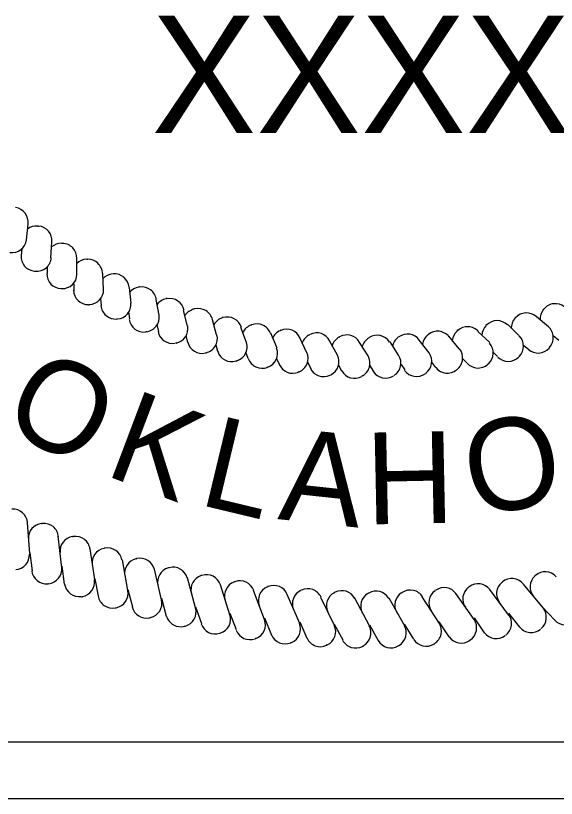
# Model space of a CAD drawing. Extents: x 1458004.1 to 1458040.9, y 194172.7 to 194198.1.
# Drawn here: x 1458038.114 to 1458038.688, y 194176.047 to 194176.879 of the extents above; entities that cross this region are included whole.
import ezdxf

# ---------------------------------------------------------------- set-up
doc = ezdxf.new("R2010")
doc.units = 0
for name, color, linetype in [('Eng_Stamp', 7, 'Continuous'), ('Eng_Stamp_Text_4', 7, 'Continuous'), ('Text_Box_4', 7, 'Continuous')]:
    doc.layers.add(name, color=color, linetype=linetype)

msp = doc.modelspace()

# ---------------------------------------------------------------- linework, layer by layer
at = {"layer": 'Eng_Stamp'}
for p, q in [((1458038.12583, 194176.64083), (1458038.1275, 194176.6575)), ((1458038.13833, 194176.655), (1458038.1375, 194176.655)), ((1458038.12083, 194176.63167), (1458038.12, 194176.62417)), ((1458038.15167, 194176.62167), (1458038.1525, 194176.63833)), ((1458038.16417, 194176.63667), (1458038.16333, 194176.63667)), ((1458038.17917, 194176.60417), (1458038.17917, 194176.62083)), ((1458038.19083, 194176.62), (1458038.19, 194176.62)), ((1458038.13417, 194176.6075), (1458038.135, 194176.6075)), ((1458038.1475, 194176.6125), (1458038.1475, 194176.605)), ((1458038.2075, 194176.5875), (1458038.20667, 194176.605)), ((1458038.2175, 194176.60417), (1458038.2175, 194176.60417)), ((1458038.17583, 194176.59417), (1458038.17583, 194176.58667)), ((1458038.23667, 194176.57333), (1458038.235, 194176.59)), ((1458038.24583, 194176.59083), (1458038.245, 194176.59083)), ((1458038.1625, 194176.58833), (1458038.16333, 194176.58917)), ((1458038.20417, 194176.57833), (1458038.205, 194176.57083)), ((1458038.26667, 194176.56083), (1458038.26333, 194176.5775)), ((1458038.275, 194176.57833), (1458038.27417, 194176.57833)), ((1458038.19167, 194176.57167), (1458038.1925, 194176.57167)), ((1458038.29667, 194176.54917), (1458038.2925, 194176.56583)), ((1458038.30417, 194176.5675), (1458038.30333, 194176.5675)), ((1458038.675, 194176.5675), (1458038.67417, 194176.56667)), ((1458038.22167, 194176.55667), (1458038.2225, 194176.55667)), ((1458038.23417, 194176.56417), (1458038.235, 194176.55667)), ((1458038.33417, 194176.55833), (1458038.33333, 194176.55833)), ((1458038.645, 194176.55833), (1458038.64417, 194176.5575)), ((1458038.68, 194176.54833), (1458038.66667, 194176.55917)), ((1458038.26417, 194176.55083), (1458038.26583, 194176.54333)), ((1458038.3275, 194176.54), (1458038.32333, 194176.55583)), ((1458038.365, 194176.55083), (1458038.36417, 194176.55)), ((1458038.61417, 194176.55083), (1458038.61333, 194176.55)), ((1458038.64833, 194176.53917), (1458038.63667, 194176.55083)), ((1458038.2525, 194176.54333), (1458038.25333, 194176.54333)), ((1458038.35917, 194176.53167), (1458038.35333, 194176.5475)), ((1458038.39167, 194176.52583), (1458038.385, 194176.54167)), ((1458038.39583, 194176.545), (1458038.395, 194176.54417)), ((1458038.42667, 194176.54), (1458038.42583, 194176.54)), ((1458038.5525, 194176.54), (1458038.55167, 194176.54)), ((1458038.58333, 194176.545), (1458038.5825, 194176.54417)), ((1458038.6175, 194176.53167), (1458038.605, 194176.54333)), ((1458038.28417, 194176.53083), (1458038.285, 194176.53167)), ((1458038.295, 194176.53917), (1458038.29667, 194176.53167)), ((1458038.42333, 194176.52083), (1458038.41583, 194176.53667)), ((1458038.45583, 194176.51833), (1458038.4475, 194176.53333)), ((1458038.45833, 194176.5375), (1458038.4575, 194176.5375)), ((1458038.48833, 194176.5175), (1458038.47917, 194176.53167)), ((1458038.49, 194176.53667), (1458038.48917, 194176.53667)), ((1458038.52083, 194176.51833), (1458038.51167, 194176.5325)), ((1458038.52083, 194176.5375), (1458038.52, 194176.5375)), ((1458038.55333, 194176.52083), (1458038.5425, 194176.53417)), ((1458038.585, 194176.525), (1458038.57417, 194176.53833)), ((1458038.685, 194176.53917), (1458038.69083, 194176.53417)), ((1458038.32667, 194176.52917), (1458038.32833, 194176.5225)), ((1458038.6525, 194176.52917), (1458038.65833, 194176.525)), ((1458038.68083, 194176.52583), (1458038.68083, 194176.52667)), ((1458038.31583, 194176.52083), (1458038.31667, 194176.52083)), ((1458038.35833, 194176.52167), (1458038.36083, 194176.515)), ((1458038.39083, 194176.515), (1458038.39417, 194176.50833)), ((1458038.58833, 194176.515), (1458038.59333, 194176.51)), ((1458038.62083, 194176.52167), (1458038.62583, 194176.51667)), ((1458038.64833, 194176.51667), (1458038.64917, 194176.51667)), ((1458038.34833, 194176.51167), (1458038.34917, 194176.5125)), ((1458038.42417, 194176.51083), (1458038.4275, 194176.50417)), ((1458038.45667, 194176.50833), (1458038.46, 194176.50167)), ((1458038.49, 194176.5075), (1458038.49417, 194176.50083)), ((1458038.52333, 194176.50833), (1458038.5275, 194176.5025)), ((1458038.55583, 194176.51083), (1458038.56, 194176.505)), ((1458038.615, 194176.50833), (1458038.61583, 194176.50917)), ((1458038.38083, 194176.505), (1458038.38167, 194176.50583)), ((1458038.41417, 194176.5), (1458038.415, 194176.50083)), ((1458038.54917, 194176.49833), (1458038.55, 194176.49917)), ((1458038.5825, 194176.5025), (1458038.58333, 194176.50333)), ((1458038.44833, 194176.4975), (1458038.44917, 194176.4975)), ((1458038.48167, 194176.49583), (1458038.4825, 194176.49667)), ((1458038.51583, 194176.49667), (1458038.51583, 194176.49667)), ((1458038.12917, 194176.3075), (1458038.12667, 194176.34)), ((1458038.1425, 194176.33917), (1458038.14167, 194176.33917)), ((1458038.16333, 194176.2925), (1458038.15917, 194176.32583)), ((1458038.175, 194176.32583), (1458038.175, 194176.325)), ((1458038.12917, 194176.30833), (1458038.13167, 194176.28917)), ((1458038.19833, 194176.28), (1458038.19333, 194176.3125)), ((1458038.20917, 194176.31333), (1458038.20833, 194176.31333)), ((1458038.23333, 194176.26833), (1458038.2275, 194176.30083)), ((1458038.2425, 194176.3025), (1458038.24167, 194176.30167)), ((1458038.16333, 194176.29417), (1458038.16583, 194176.275)), ((1458038.26917, 194176.25833), (1458038.26167, 194176.29083)), ((1458038.2775, 194176.2925), (1458038.27667, 194176.2925)), ((1458038.31167, 194176.28417), (1458038.31083, 194176.28417)), ((1458038.66583, 194176.28417), (1458038.665, 194176.28333)), ((1458038.14833, 194176.27583), (1458038.14917, 194176.27583)), ((1458038.19833, 194176.28083), (1458038.20167, 194176.2625)), ((1458038.305, 194176.25), (1458038.29667, 194176.28167)), ((1458038.34167, 194176.2425), (1458038.33167, 194176.27417)), ((1458038.34667, 194176.2775), (1458038.34583, 194176.2775)), ((1458038.63083, 194176.2775), (1458038.63083, 194176.27667)), ((1458038.67417, 194176.25), (1458038.65333, 194176.275)), ((1458038.23333, 194176.26917), (1458038.23833, 194176.25083)), ((1458038.37833, 194176.2375), (1458038.36667, 194176.26833)), ((1458038.3825, 194176.2725), (1458038.38167, 194176.2725)), ((1458038.4175, 194176.26833), (1458038.41667, 194176.26833)), ((1458038.45333, 194176.26667), (1458038.4525, 194176.26583)), ((1458038.48917, 194176.26583), (1458038.48833, 194176.265)), ((1458038.525, 194176.26667), (1458038.52417, 194176.26583)), ((1458038.56, 194176.26833), (1458038.55917, 194176.26833)), ((1458038.59583, 194176.2725), (1458038.595, 194176.27167)), ((1458038.6375, 194176.2425), (1458038.6175, 194176.26917)), ((1458038.18417, 194176.26167), (1458038.185, 194176.26167)), ((1458038.26917, 194176.26), (1458038.27417, 194176.24083)), ((1458038.41583, 194176.23333), (1458038.4025, 194176.26417)), ((1458038.4525, 194176.23167), (1458038.43833, 194176.26083)), ((1458038.49, 194176.23083), (1458038.47417, 194176.26)), ((1458038.52667, 194176.23167), (1458038.51083, 194176.26)), ((1458038.56417, 194176.23333), (1458038.54583, 194176.26167)), ((1458038.60083, 194176.2375), (1458038.58167, 194176.265)), ((1458038.22, 194176.25), (1458038.22083, 194176.25)), ((1458038.305, 194176.25083), (1458038.31167, 194176.23333)), ((1458038.67333, 194176.25083), (1458038.68667, 194176.23667)), ((1458038.34167, 194176.24417), (1458038.34833, 194176.22667)), ((1458038.6375, 194176.24417), (1458038.64917, 194176.22917)), ((1458038.25667, 194176.23917), (1458038.2575, 194176.24)), ((1458038.37833, 194176.23917), (1458038.38583, 194176.22083)), ((1458038.41583, 194176.235), (1458038.42333, 194176.2175)), ((1458038.4525, 194176.2325), (1458038.46167, 194176.21583)), ((1458038.52667, 194176.2325), (1458038.53667, 194176.21667)), ((1458038.56333, 194176.235), (1458038.57417, 194176.21917)), ((1458038.60083, 194176.23917), (1458038.61167, 194176.22333)), ((1458038.29333, 194176.23), (1458038.29417, 194176.23083)), ((1458038.49, 194176.23167), (1458038.49917, 194176.215)), ((1458038.67167, 194176.2275), (1458038.67167, 194176.2275)), ((1458038.33083, 194176.2225), (1458038.33167, 194176.22333)), ((1458038.36833, 194176.2175), (1458038.36917, 194176.2175)), ((1458038.59583, 194176.215), (1458038.59667, 194176.21583)), ((1458038.63417, 194176.22083), (1458038.63417, 194176.22083)), ((1458038.40667, 194176.2125), (1458038.40667, 194176.21333)), ((1458038.44417, 194176.21), (1458038.445, 194176.21083)), ((1458038.4825, 194176.20917), (1458038.48333, 194176.20917)), ((1458038.52083, 194176.20917), (1458038.52083, 194176.21)), ((1458038.55833, 194176.21167), (1458038.55917, 194176.21167))]:
    msp.add_line(p, q, dxfattribs=at)
for centre, start, end in [((1458038.11188, 194176.65959), 352.21112, 82.21112), ((1458038.13634, 194176.63987), 85.31452, 128.34659), ((1458038.1372, 194176.6398), 355.31452, 85.31452), ((1458038.11023, 194176.64273), 262.21112, 352.21112), ((1458038.1627, 194176.62144), 88.41792, 131.44999), ((1458038.16356, 194176.62141), 358.41792, 88.41792), ((1458038.13561, 194176.62294), 175.31452, 265.31452), ((1458038.13647, 194176.62287), 265.31452, 355.31452), ((1458038.19002, 194176.60445), 91.52132, 134.55339), ((1458038.19088, 194176.60448), 1.52132, 91.52132), ((1458038.16288, 194176.60449), 178.41792, 268.41792), ((1458038.16375, 194176.60447), 268.41792, 358.41792), ((1458038.21821, 194176.58897), 94.62472, 137.65679), ((1458038.21908, 194176.58904), 4.62472, 94.62472), ((1458038.24721, 194176.57504), 97.72812, 140.76019), ((1458038.24806, 194176.57516), 7.72812, 97.72812), ((1458038.19112, 194176.58754), 181.52132, 271.52132), ((1458038.19198, 194176.58757), 271.52132, 1.52132), ((1458038.22109, 194176.57222), 274.62472, 4.62472), ((1458038.27691, 194176.5627), 100.83152, 143.86359), ((1458038.27776, 194176.56286), 10.83152, 100.83152), ((1458038.68704, 194176.55739), 51.17572, 141.17572), ((1458038.22023, 194176.57215), 184.62472, 274.62472), ((1458038.30724, 194176.55199), 103.93492, 146.96699), ((1458038.30808, 194176.55219), 13.93492, 103.93492), ((1458038.6865, 194176.55672), 141.17572, 184.20779), ((1458038.25013, 194176.55835), 187.72812, 277.72812), ((1458038.25099, 194176.55847), 277.72812, 7.72812), ((1458038.33811, 194176.54293), 107.03832, 150.07039), ((1458038.33893, 194176.54318), 17.03832, 107.03832), ((1458038.65587, 194176.5469), 138.07232, 181.10439), ((1458038.65645, 194176.54754), 48.07232, 138.07232), ((1458038.28158, 194176.54635), 280.83152, 10.83152), ((1458038.36942, 194176.53556), 110.14172, 153.17379), ((1458038.37023, 194176.53585), 20.14172, 110.14172), ((1458038.59388, 194176.53287), 41.86552, 131.86552), ((1458038.62475, 194176.53874), 134.96892, 178.00099), ((1458038.62536, 194176.53936), 44.96892, 134.96892), ((1458038.66948, 194176.53671), 318.07232, 48.07232), ((1458038.28073, 194176.54619), 190.83152, 280.83152), ((1458038.31279, 194176.53592), 283.93492, 13.93492), ((1458038.40108, 194176.52989), 113.24512, 156.27719), ((1458038.40187, 194176.53023), 23.24512, 113.24512), ((1458038.433, 194176.52595), 116.34852, 159.38059), ((1458038.43378, 194176.52633), 26.34852, 116.34852), ((1458038.46585, 194176.52416), 29.45192, 119.45192), ((1458038.5301, 194176.52504), 35.65872, 125.65872), ((1458038.56142, 194176.52755), 128.76212, 171.79419), ((1458038.5621, 194176.52809), 38.76212, 128.76212), ((1458038.59324, 194176.53229), 131.86552, 174.89759), ((1458038.31195, 194176.53571), 193.93492, 283.93492), ((1458038.34452, 194176.52718), 287.03832, 17.03832), ((1458038.46509, 194176.52374), 119.45192, 162.48399), ((1458038.49726, 194176.52327), 122.55532, 165.58739), ((1458038.49799, 194176.52373), 32.55532, 122.55532), ((1458038.5294, 194176.52454), 125.65872, 168.69079), ((1458038.63779, 194176.52784), 314.96892, 44.96892), ((1458038.37667, 194176.52018), 290.14172, 20.14172), ((1458038.57321, 194176.5153), 308.76212, 38.76212), ((1458038.60567, 194176.52069), 311.86552, 41.86552), ((1458038.6689, 194176.53607), 228.07232, 318.07232), ((1458038.34369, 194176.52693), 197.03832, 287.03832), ((1458038.40916, 194176.51493), 293.24512, 23.24512), ((1458038.44188, 194176.51145), 296.34852, 26.34852), ((1458038.47474, 194176.50974), 299.45192, 29.45192), ((1458038.50765, 194176.50981), 302.55532, 32.55532), ((1458038.5405, 194176.51167), 305.65872, 35.65872), ((1458038.63718, 194176.52723), 224.96892, 314.96892), ((1458038.37586, 194176.51988), 200.14172, 290.14172), ((1458038.40836, 194176.51459), 203.24512, 293.24512), ((1458038.60503, 194176.52011), 221.86552, 311.86552), ((1458038.4411, 194176.51106), 206.34852, 296.34852), ((1458038.47399, 194176.50931), 209.45192, 299.45192), ((1458038.50692, 194176.50934), 212.55532, 302.55532), ((1458038.5398, 194176.51116), 215.65872, 305.65872), ((1458038.57253, 194176.51475), 218.76212, 308.76212), ((1458038.11123, 194176.33912), 3.6, 93.6), ((1458038.1433, 194176.32387), 96, 183.38537), ((1458038.14416, 194176.32396), 6, 96), ((1458038.17683, 194176.31007), 98.4, 185.78537), ((1458038.17769, 194176.31019), 8.4, 98.4), ((1458038.11327, 194176.30605), 273.6, 3.6), ((1458038.21092, 194176.29768), 100.8, 188.18538), ((1458038.21177, 194176.29784), 10.8, 100.8), ((1458038.2455, 194176.28673), 103.2, 190.58537), ((1458038.24634, 194176.28693), 13.2, 103.2), ((1458038.14759, 194176.29101), 276, 6), ((1458038.2805, 194176.27724), 105.6, 192.98537), ((1458038.28133, 194176.27747), 15.6, 105.6), ((1458038.14672, 194176.29092), 186, 276), ((1458038.31587, 194176.26922), 108, 195.38538), ((1458038.31669, 194176.26949), 18, 108), ((1458038.67592, 194176.27191), 132, 219.38537), ((1458038.67656, 194176.27249), 42, 132), ((1458038.18164, 194176.27728), 188.4, 278.4), ((1458038.1825, 194176.27741), 278.4, 8.4), ((1458038.35154, 194176.26269), 110.4, 197.78537), ((1458038.35236, 194176.26299), 20.4, 110.4), ((1458038.38826, 194176.258), 22.8, 112.8), ((1458038.60519, 194176.25981), 37.2, 127.2), ((1458038.64034, 194176.26485), 129.6, 216.98538), ((1458038.64101, 194176.2654), 39.6, 129.6), ((1458038.21794, 194176.26529), 280.8, 10.8), ((1458038.38746, 194176.25766), 112.8, 200.18538), ((1458038.42356, 194176.25414), 115.2, 202.58538), ((1458038.42434, 194176.25451), 25.2, 115.2), ((1458038.45977, 194176.25213), 117.6, 204.98538), ((1458038.46054, 194176.25253), 27.6, 117.6), ((1458038.49678, 194176.25208), 30, 120), ((1458038.53229, 194176.25267), 122.4, 209.78537), ((1458038.53302, 194176.25314), 32.4, 122.4), ((1458038.56847, 194176.25522), 124.8, 212.18537), ((1458038.56918, 194176.25572), 34.8, 124.8), ((1458038.60451, 194176.25928), 127.2, 214.58538), ((1458038.21709, 194176.26513), 190.8, 280.8), ((1458038.25387, 194176.25466), 283.2, 13.2), ((1458038.49603, 194176.25164), 120, 207.38538), ((1458038.25303, 194176.25446), 193.2, 283.2), ((1458038.29021, 194176.24555), 285.6, 15.6), ((1458038.6621, 194176.23985), 309.6, 39.6), ((1458038.28938, 194176.24532), 195.6, 285.6), ((1458038.3269, 194176.23797), 288, 18), ((1458038.6252, 194176.23339), 307.2, 37.2), ((1458038.32608, 194176.2377), 198, 288), ((1458038.36387, 194176.23192), 290.4, 20.4), ((1458038.40107, 194176.22744), 292.8, 22.8), ((1458038.55074, 194176.22514), 302.4, 32.4), ((1458038.58806, 194176.22849), 304.8, 34.8), ((1458038.69806, 194176.24726), 222, 312), ((1458038.36306, 194176.23162), 200.4, 290.4), ((1458038.43842, 194176.22451), 295.2, 25.2), ((1458038.47586, 194176.22315), 297.6, 27.6), ((1458038.51332, 194176.22336), 300, 30), ((1458038.66144, 194176.2393), 219.6, 309.6), ((1458038.40027, 194176.2271), 202.8, 292.8), ((1458038.43763, 194176.22414), 205.2, 295.2), ((1458038.47509, 194176.22275), 207.6, 297.6), ((1458038.55001, 194176.22468), 212.4, 302.4), ((1458038.58735, 194176.22799), 214.8, 304.8), ((1458038.62451, 194176.23287), 217.2, 307.2), ((1458038.51257, 194176.22293), 210, 300)]:
    msp.add_arc(centre, 0.01558, start, end, dxfattribs=at)
at = {"layer": 'Text_Box_4'}
for p, q in [((1458032.09667, 194176.1075), (1458039.4, 194176.1075)), ((1458035.87833, 194176.0475), (1458039.4, 194176.0475))]:
    msp.add_line(p, q, dxfattribs=at)

# ---------------------------------------------------------------- texts
at = {"layer": 'Eng_Stamp_Text_4'}
msp.add_text('XXXXX', height=0.124675, dxfattribs=at).set_placement((1458038.25842, 194176.75417))
for s, height, rotation, p in [('O', 0.09749, 331.10901, (1458038.09583, 194176.445)), ('K', 0.09749, 339.30976, (1458038.20667, 194176.39167)), ('L', 0.09748, 346.50956, (1458038.30667, 194176.36)), ('O', 0.09749, 10.51184, (1458038.6, 194176.34583)), ('A', 0.09749, 353.93956, (1458038.39167, 194176.34417)), ('H', 0.09749, 1.16247, (1458038.48667, 194176.33833))]:
    msp.add_text(s, height=height, rotation=rotation, dxfattribs=at).set_placement(p)

doc.saveas('drawing.dxf')
